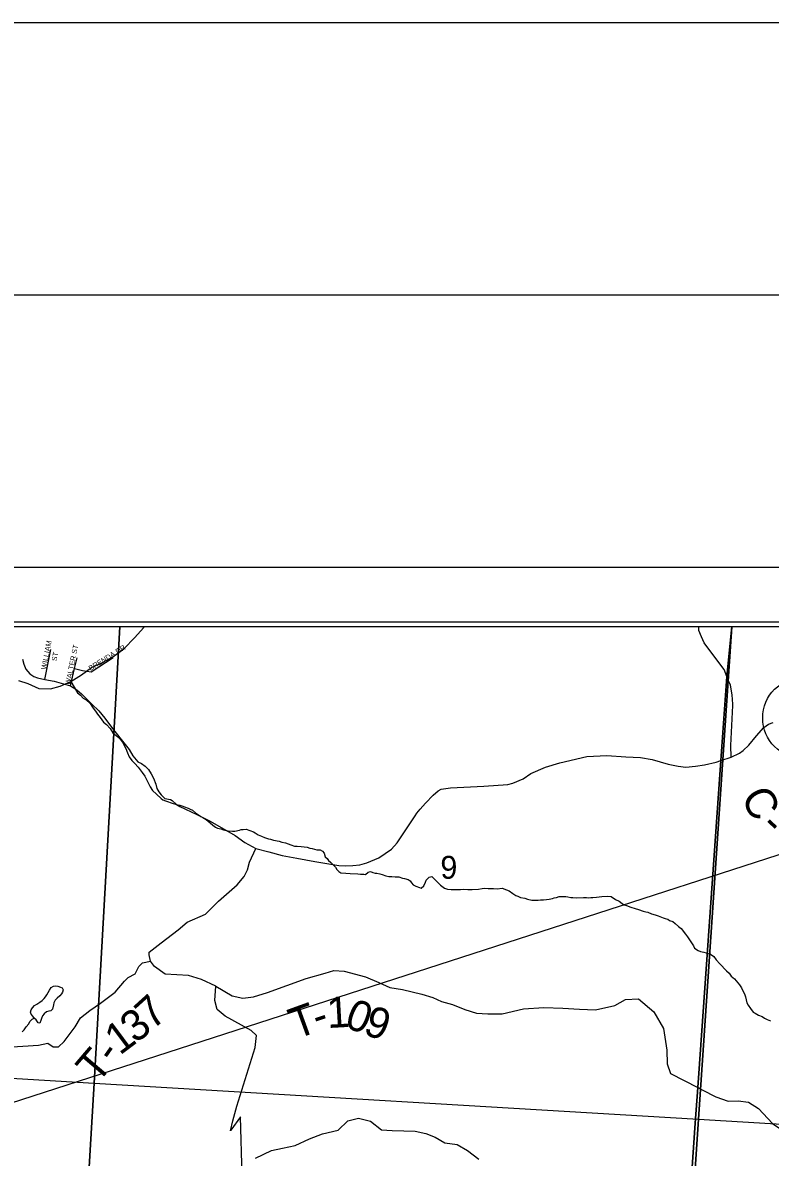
# Model space of a CAD drawing. Extents: x 0 to 34, y 0 to 22.
# Drawn here: x 4.684 to 6.056, y 19.917 to 22 of the extents above; entities that cross this region are included whole.
import ezdxf

# ---------------------------------------------------------------- set-up
doc = ezdxf.new("R2010")
doc.units = 0
for name, color, linetype in [('GM_X_County', 7, 'Continuous'), ('GM_X_County_Road', 7, 'Continuous'), ('GM_X_County_Road_Text', 7, 'Continuous'), ('GM_X_Minor_River', 7, 'Continuous'), ('GM_X_Section', 7, 'Continuous'), ('GM_X_Section_Text', 7, 'Continuous'), ('GM_X_State_Route', 7, 'Continuous'), ('GM_X_Township', 7, 'Continuous'), ('GM_X_Township_Road', 7, 'Continuous'), ('GM_X_Township_Road_Text', 7, 'Continuous'), ('GM_X_Township_ROW', 7, 'Continuous'), ('GM_X_Township_Subdivision', 7, 'Continuous'), ('GM_X_Township_Subdivision_Text', 7, 'Continuous'), ('GM_X_Unincorporated', 7, 'Continuous'), ('GM_X_US_Route', 7, 'Continuous'), ('SH_Border', 7, 'Continuous'), ('SH_Cut_Line', 7, 'Continuous'), ('SH_Data', 7, 'Continuous')]:
    doc.layers.add(name, color=color, linetype=linetype)

msp = doc.modelspace()

# ---------------------------------------------------------------- linework, layer by layer
at = {"layer": 'GM_X_County'}
msp.add_lwpolyline([(8.9084, 15.63), (8.9084, 20.8908), (2.1084, 20.8908), (2.1084, 19.9847)], dxfattribs=at)
at = {"layer": 'GM_X_County_Road'}
for points in [[(5.0661, 19.9663), (5.0651, 19.965), (5.0699, 19.9834), (5.0771, 20.0105), (5.1106, 20.1184), (5.113, 20.14), (5.1034, 20.1496), (5.0555, 20.176), (5.0411, 20.188), (5.0363, 20.2047), (5.0387, 20.2311), (5.0123, 20.2431), (4.9883, 20.2503), (4.9451, 20.2527), (4.9259, 20.2671), (4.9187, 20.2767), (4.9163, 20.2886), (4.9163, 20.2935), (4.9379, 20.3102), (4.9691, 20.3342), (4.9859, 20.3486), (5.0195, 20.363), (5.0435, 20.387), (5.0778, 20.4168), (5.0904, 20.432), (5.0965, 20.4443), (5.1005, 20.4587), (5.1119, 20.4835)], [(5.0867, 19.8834), (5.0839, 19.9908), (5.0661, 19.9663)]]:
    msp.add_lwpolyline(points, dxfattribs=at)
at = {"layer": 'GM_X_Minor_River'}
for points in [[(4.6759, 20.792), (4.6933, 20.7866), (4.7137, 20.7774), (4.7349, 20.7766), (4.7524, 20.7819), (4.7721, 20.7901), (4.7918, 20.8022), (4.8101, 20.8158), (4.8313, 20.8256), (4.8495, 20.8354), (4.8693, 20.8505), (4.8898, 20.871), (4.9058, 20.8891), (4.9069, 20.8908)], [(4.7721, 20.7901), (4.7846, 20.7697), (4.7902, 20.7654), (4.7947, 20.7596), (4.8003, 20.7565), (4.8078, 20.7499), (4.8122, 20.743), (4.8185, 20.7338), (4.8211, 20.7303), (4.8262, 20.7242), (4.8322, 20.7153), (4.8378, 20.7115), (4.8444, 20.7037), (4.8496, 20.6957), (4.8586, 20.6887), (4.8627, 20.6845), (4.8682, 20.6771), (4.8704, 20.6729), (4.8733, 20.6672), (4.8762, 20.6595), (4.8795, 20.6519), (4.8843, 20.645), (4.8899, 20.6396), (4.8959, 20.633), (4.9033, 20.6234), (4.9081, 20.6165), (4.9128, 20.6065), (4.9179, 20.5966), (4.9224, 20.5904), (4.9294, 20.5831), (4.938, 20.5754), (4.9414, 20.573), (4.9463, 20.5714), (4.9497, 20.5702), (4.9561, 20.5675), (4.9598, 20.5663), (4.9685, 20.5635), (4.9723, 20.563), (4.976, 20.5622), (4.9809, 20.5602), (4.9877, 20.5578), (4.9911, 20.5559), (4.9956, 20.5539), (5.0012, 20.5489), (5.0109, 20.5422), (5.0143, 20.5407), (5.0207, 20.5368), (5.0281, 20.5309), (5.033, 20.5267), (5.0378, 20.5228), (5.0416, 20.5212), (5.0473, 20.5196), (5.0522, 20.518), (5.0574, 20.5168), (5.0608, 20.5163), (5.0688, 20.5155), (5.0733, 20.5154), (5.0817, 20.5175), (5.0851, 20.5182), (5.0885, 20.5185), (5.0938, 20.5188), (5.1074, 20.514), (5.1108, 20.5125), (5.116, 20.509), (5.122, 20.5062), (5.128, 20.5038), (5.1352, 20.5014), (5.1386, 20.5006), (5.1442, 20.4986), (5.1548, 20.4969), (5.1597, 20.4953), (5.1665, 20.4941), (5.1759, 20.4905), (5.1827, 20.4881), (5.1876, 20.4877), (5.1948, 20.4872), (5.2008, 20.4867), (5.2061, 20.4858), (5.211, 20.4842), (5.2152, 20.4838), (5.2239, 20.4814), (5.2299, 20.4809), (5.234, 20.4785), (5.2374, 20.4751), (5.2392, 20.4686), (5.2429, 20.4651), (5.2455, 20.4616), (5.2492, 20.4585), (5.2578, 20.4496), (5.2603, 20.445), (5.2644, 20.4412), (5.2678, 20.4392), (5.2773, 20.4383), (5.2848, 20.4374), (5.2992, 20.4372), (5.3037, 20.4367), (5.3098, 20.4363), (5.3132, 20.4358), (5.3182, 20.4399)], [(5.3182, 20.4399), (5.3224, 20.4414), (5.3269, 20.4398), (5.3307, 20.4386), (5.3341, 20.4381), (5.3394, 20.4373), (5.3435, 20.4361), (5.3503, 20.4337), (5.3559, 20.4324), (5.3612, 20.432), (5.3677, 20.4315), (5.3745, 20.4314), (5.3809, 20.4294), (5.385, 20.4285), (5.3915, 20.4269), (5.3952, 20.4242), (5.3978, 20.4204), (5.4007, 20.4169), (5.4056, 20.4145), (5.412, 20.4118), (5.4154, 20.411), (5.42, 20.4151), (5.4232, 20.4215), (5.4244, 20.4256), (5.4298, 20.4312), (5.4351, 20.4323), (5.444, 20.423), (5.4511, 20.4161), (5.4582, 20.4106), (5.4635, 20.409), (5.4703, 20.4081), (5.4752, 20.4084), (5.4877, 20.4082), (5.4934, 20.4089), (5.501, 20.4084), (5.5089, 20.4086), (5.5203, 20.4092), (5.5271, 20.4102), (5.5309, 20.4105), (5.5381, 20.41), (5.548, 20.4103), (5.5548, 20.4098), (5.5639, 20.4108), (5.5718, 20.408), (5.5767, 20.4056), (5.5838, 20.4009), (5.5894, 20.3974), (5.5928, 20.3962), (5.5977, 20.3939), (5.6056, 20.3922), (5.6105, 20.3906), (5.6184, 20.3886), (5.6218, 20.3889), (5.6302, 20.3888), (5.6343, 20.3891), (5.64, 20.3894), (5.6453, 20.39), (5.6503, 20.3907), (5.6564, 20.3917), (5.6598, 20.3928), (5.664, 20.3939), (5.6685, 20.3953), (5.675, 20.3956), (5.681, 20.3955), (5.6844, 20.3951), (5.6901, 20.3938), (5.6935, 20.3934), (5.7003, 20.3933), (5.7132, 20.3938), (5.7189, 20.3934), (5.7227, 20.3933), (5.7268, 20.3936), (5.7306, 20.3939), (5.7371, 20.3942), (5.7473, 20.3952), (5.7572, 20.3958), (5.764, 20.3956), (5.7722, 20.3898), (5.7786, 20.387), (5.7842, 20.3828), (5.788, 20.3801), (5.7925, 20.3788), (5.8, 20.3761), (5.8079, 20.3736), (5.8143, 20.3716), (5.8226, 20.3688), (5.8279, 20.3676), (5.8317, 20.3668), (5.8384, 20.3636), (5.8452, 20.3616), (5.8505, 20.36), (5.8595, 20.3565), (5.8633, 20.3553), (5.8682, 20.354), (5.8715, 20.3513), (5.8772, 20.3493), (5.8817, 20.3458), (5.8876, 20.3404), (5.8929, 20.3365), (5.9003, 20.3265), (5.904, 20.3215)], [(5.904, 20.3215), (5.9092, 20.3142), (5.915, 20.305), (5.9172, 20.3004), (5.924, 20.2965), (5.9281, 20.2945), (5.9342, 20.2933), (5.9387, 20.2921), (5.9462, 20.2897), (5.9526, 20.285), (5.957, 20.2789), (5.9637, 20.2719), (5.9756, 20.2588), (5.9808, 20.2549), (5.9845, 20.2492), (5.9905, 20.2445), (5.9998, 20.233), (6.0031, 20.228), (6.0093, 20.215), (6.0107, 20.2111), (6.0118, 20.2058), (6.0132, 20.2001), (6.0158, 20.1959), (6.0198, 20.1897), (6.0246, 20.1832), (6.0284, 20.1812), (6.0344, 20.1777), (6.0412, 20.1749), (6.0457, 20.1722), (6.0505, 20.1695), (6.0569, 20.1671)], [(4.6827, 20.1471), (4.6866, 20.1509), (4.6901, 20.1561), (4.6951, 20.1614), (4.6971, 20.1659), (4.7013, 20.17), (4.7048, 20.1718), (4.7022, 20.1757), (4.6992, 20.1795), (4.6981, 20.183), (4.6994, 20.1871), (4.7017, 20.1913), (4.7056, 20.1954), (4.7101, 20.1976), (4.7155, 20.2017), (4.7194, 20.2046), (4.7232, 20.208), (4.7259, 20.2114), (4.7283, 20.2147), (4.7306, 20.2192), (4.7333, 20.2234), (4.7361, 20.2283), (4.7407, 20.2308)], [(4.7407, 20.2308), (4.7441, 20.2315), (4.7486, 20.2307), (4.7531, 20.2291), (4.7565, 20.2275), (4.758, 20.2241), (4.7568, 20.2199), (4.7548, 20.2166), (4.7521, 20.2132), (4.7471, 20.2087), (4.7432, 20.2054), (4.7413, 20.2005), (4.7404, 20.1963), (4.7388, 20.1887), (4.7353, 20.1854), (4.7319, 20.1847), (4.7277, 20.1836), (4.7235, 20.1803), (4.72, 20.1761), (4.7184, 20.1716), (4.7172, 20.1678), (4.7156, 20.1629), (4.7122, 20.1637), (4.7085, 20.1687), (4.7048, 20.1718)], [(5.1115, 19.9152), (5.1403, 19.9288), (5.1608, 19.9333), (5.1843, 19.9385), (5.2101, 19.9506), (5.2344, 19.9596), (5.2632, 19.9663), (5.2807, 19.9837), (5.3004, 19.9882), (5.3223, 19.9828), (5.3427, 19.9668), (5.3624, 19.966), (5.3836, 19.9652), (5.4041, 19.9643), (5.4237, 19.9605), (5.4411, 19.9536), (5.4585, 19.9429), (5.4812, 19.9398), (5.5001, 19.9291), (5.5212, 19.9131)]]:
    msp.add_lwpolyline(points, dxfattribs=at)
at = {"layer": 'GM_X_Section'}
for p, q in [((4.8624, 20.8908), (3.7825, 20.8908)), ((5.9857, 20.8908), (4.8624, 20.8908)), ((7.0909, 20.8908), (5.9857, 20.8908))]:
    msp.add_line(p, q, dxfattribs=at)
for points in [[(3.7825, 20.8908), (3.731, 20.118), (4.8149, 20.0525), (4.8624, 20.8908)], [(4.8624, 20.8908), (4.8149, 20.0525), (5.9246, 19.9867), (5.9857, 20.8908)], [(5.9857, 20.8908), (5.9246, 19.9867), (7.0324, 19.92), (7.0909, 20.8908)]]:
    msp.add_lwpolyline(points, dxfattribs=at)
for points in [[(4.8149, 20.0525), (4.754, 19.0266), (3.6625, 19.0898), (3.731, 20.118)], [(5.9246, 19.9867), (5.8561, 18.9573), (4.754, 19.0266), (4.8149, 20.0525)], [(7.0324, 19.92), (6.9681, 18.8952), (5.8561, 18.9573), (5.9246, 19.9867)]]:
    msp.add_lwpolyline(points, close=True, dxfattribs=at)
at = {"layer": 'GM_X_State_Route'}
for points in [[(4.6833, 20.8314), (4.6859, 20.8219), (4.6894, 20.8128), (4.6968, 20.8043), (4.7042, 20.7997), (4.7113, 20.7972), (4.7242, 20.7939), (4.7418, 20.791), (4.7547, 20.7874), (4.7715, 20.7823), (4.7834, 20.7749), (4.7916, 20.7678), (4.8106, 20.7489), (4.8239, 20.7364), (4.8348, 20.7229), (4.8506, 20.7017), (4.8698, 20.6775), (4.8792, 20.6654), (4.8862, 20.6539), (4.8922, 20.6463), (4.8955, 20.6429), (4.9018, 20.6398), (4.9086, 20.6346), (4.9145, 20.6285), (4.9195, 20.6208), (4.9241, 20.6127), (4.9284, 20.602), (4.9301, 20.594), (4.9335, 20.5878), (4.9378, 20.582), (4.945, 20.5753), (4.9552, 20.5736), (4.9581, 20.5718), (4.966, 20.5642), (4.9726, 20.5605), (5.0037, 20.5463), (5.0282, 20.5339), (5.0737, 20.5075), (5.0915, 20.4947), (5.1119, 20.4835), (5.1355, 20.4777), (5.1601, 20.4709), (5.187, 20.4659), (5.2203, 20.4595), (5.2641, 20.4521), (5.2761, 20.4515), (5.2901, 20.4522), (5.3028, 20.4535), (5.3158, 20.4573), (5.3374, 20.4667), (5.3608, 20.4821), (5.3714, 20.4938), (5.4042, 20.5437), (5.4075, 20.5487), (5.4136, 20.5559)], [(5.4136, 20.5559), (5.4231, 20.5669), (5.4372, 20.5813), (5.4463, 20.5892), (5.4523, 20.5923), (5.469, 20.5949), (5.5303, 20.5982), (5.5747, 20.6011), (5.5834, 20.6033), (5.6027, 20.6113), (5.6167, 20.6211), (5.6433, 20.6332), (5.6698, 20.6411), (5.7197, 20.6526), (5.7562, 20.6541), (5.7908, 20.6521), (5.8182, 20.6505), (5.8397, 20.6468), (5.8689, 20.6387), (5.8872, 20.635), (5.9014, 20.6331), (5.9192, 20.6347), (5.9355, 20.6374), (5.9567, 20.6419), (5.9657, 20.645), (5.9846, 20.6514), (5.9997, 20.6584), (6.0064, 20.6633), (6.0171, 20.6732), (6.0309, 20.6907), (6.0446, 20.7055), (6.0532, 20.7119), (6.0615, 20.7151)]]:
    msp.add_lwpolyline(points, dxfattribs=at)
at = {"layer": 'GM_X_Township'}
for points in [[(5.9855, 20.8908), (2.1084, 20.8908), (2.1084, 19.9847)], [(5.9855, 20.8908), (5.9767, 20.7996), (5.9657, 20.645), (5.923, 20.0446), (5.9184, 19.9792), (5.8482, 18.9514), (5.3841, 18.9816), (4.8908, 19.0136), (4.7488, 19.0228), (4.6863, 18.0158)], [(4.6863, 18.0158), (4.7488, 19.0228), (4.8908, 19.0136), (5.3841, 18.9816), (5.8482, 18.9514), (5.9184, 19.9792), (5.923, 20.0446), (5.9657, 20.645), (5.9767, 20.7996), (5.9855, 20.8908)], [(8.9084, 15.63), (8.9084, 20.8908), (5.9855, 20.8908)]]:
    msp.add_lwpolyline(points, dxfattribs=at)
at = {"layer": 'GM_X_Township_Road'}
for points in [[(5.9872, 20.7459), (5.9873, 20.7489), (5.9863, 20.7658), (5.9832, 20.7836), (5.9798, 20.7916), (5.9767, 20.7996), (5.9717, 20.8123), (5.9583, 20.83), (5.9351, 20.8614), (5.9298, 20.8724), (5.9253, 20.8842), (5.9252, 20.8908)], [(5.9846, 20.6514), (5.9841, 20.673), (5.9872, 20.7459)], [(4.743, 20.1192), (4.7498, 20.1192), (4.7599, 20.1293), (4.78, 20.1561), (4.79, 20.1728), (4.8068, 20.1862), (4.8269, 20.1997), (4.8537, 20.2198), (4.8705, 20.2399), (4.8772, 20.2466), (4.8906, 20.2533), (4.8973, 20.2667), (4.904, 20.2734), (4.9187, 20.2767)], [(5.0387, 20.2311), (5.0684, 20.2131), (5.0881, 20.2085), (5.1078, 20.2115), (5.1332, 20.2191), (5.2044, 20.2449), (5.2392, 20.2548), (5.2552, 20.2597), (5.2741, 20.2582), (5.3131, 20.2479), (5.3374, 20.2373), (5.3578, 20.2286), (5.3809, 20.2248), (5.4165, 20.2164), (5.4366, 20.21), (5.4525, 20.2028), (5.473, 20.1971), (5.4957, 20.1879), (5.5169, 20.1815), (5.5377, 20.18), (5.5639, 20.1803), (5.6033, 20.1894), (5.6404, 20.1917), (5.6752, 20.1906), (5.7063, 20.1887), (5.7355, 20.1875), (5.7707, 20.1955), (5.7904, 20.2061), (5.8143, 20.2076), (5.8427, 20.1837), (5.8605, 20.153), (5.8661, 20.1131), (5.8669, 20.0884), (5.8733, 20.0706), (5.923, 20.0446), (5.9309, 20.0406)], [(5.9309, 20.0406), (5.9309, 20.0405), (5.9563, 20.0273), (5.979, 20.0197), (5.9975, 20.0201), (6.0165, 20.0178), (6.0347, 20.0064), (6.06, 19.9787), (6.0911, 19.9578), (6.0987, 19.9491), (6.1112, 19.9419), (6.1237, 19.9385), (6.1362, 19.9369), (6.161, 19.9285)]]:
    msp.add_lwpolyline(points, dxfattribs=at)
at = {"layer": 'GM_X_Township_ROW'}
msp.add_lwpolyline([(4.3374, 20.0868), (4.3438, 20.0864), (4.3505, 20.0876), (4.357, 20.091), (4.3636, 20.0946), (4.3691, 20.0989), (4.3755, 20.1016), (4.3793, 20.1028), (4.3834, 20.104), (4.3876, 20.1043), (4.3948, 20.1043), (4.4038, 20.1031), (4.4154, 20.1035), (4.713, 20.1226), (4.7297, 20.1259), (4.7398, 20.1192), (4.743, 20.1192)], dxfattribs=at)
at = {"layer": 'GM_X_Township_Subdivision'}
for points in [[(4.7242, 20.7939), (4.7356, 20.8493)], [(4.7715, 20.7823), (4.779, 20.8143), (4.7836, 20.8339)], [(4.779, 20.8143), (4.7939, 20.8107), (4.8097, 20.8082), (4.8502, 20.8341)]]:
    msp.add_lwpolyline(points, dxfattribs=at)
at = {"layer": 'GM_X_Unincorporated'}
msp.add_circle((6.1167, 20.7233), 0.0744, dxfattribs=at)
at = {"layer": 'GM_X_US_Route'}
msp.add_lwpolyline([(7.1693, 20.827), (4.6185, 20.0016)], dxfattribs=at)
at = {"layer": 'SH_Border'}
msp.add_lwpolyline([(1.5, 21.5), (33.5, 21.5), (33.5, 0.5), (1.5, 0.5)], close=True, dxfattribs=at)
at = {"layer": 'SH_Cut_Line'}
msp.add_lwpolyline([(0, 0), (34, 0), (34, 22), (0, 22)], close=True, dxfattribs=at)
at = {"layer": 'SH_Data'}
for p, q in [((2, 21), (9, 21)), ((2.1, 20.9), (8.9, 20.9))]:
    msp.add_line(p, q, dxfattribs=at)

# ---------------------------------------------------------------- texts
at = {"layer": 'GM_X_County_Road_Text'}
for s, rotation, p in [('C', 298.2217, (6.0011, 20.5782)), ('-', 316.97, (6.0355, 20.5211))]:
    msp.add_text(s, height=0.0568, rotation=rotation, dxfattribs=at).set_placement(p)
at = {"layer": 'GM_X_Section_Text'}
msp.add_text('9', height=0.0419, rotation=0, dxfattribs=at).set_placement((5.4506, 20.4281))
at = {"layer": 'GM_X_Township_Road_Text'}
for s, rotation, p in [('7', 42.1376, (4.9221, 20.1489)), ('1', 3.2092, (5.2435, 20.1538)), ('T', 19.8984, (5.1857, 20.1329)), ('0', 338.9561, (5.2722, 20.1568)), ('9', 340.7228, (5.3067, 20.1435)), ('3', 37.7367, (4.8908, 20.1244)), ('-', 18.3664, (5.2252, 20.1472)), ('1', 36.7731, (4.8619, 20.1028)), ('T', 49.6158, (4.8208, 20.05)), ('-', 55.1548, (4.8519, 20.0871))]:
    msp.add_text(s, height=0.0568, rotation=rotation, dxfattribs=at).set_placement(p)
at = {"layer": 'GM_X_Township_Subdivision_Text'}
for s, rotation, p in [('WILLIAM', 78.8733, (4.7268, 20.8117)), ('WALTER ST', 78.4066, (4.771, 20.7834)), ('BRENDA DR', 31.9307, (4.8085, 20.8095)), ('ST', 79.3727, (4.7461, 20.827))]:
    msp.add_text(s, height=0.00947, rotation=rotation, dxfattribs=at).set_placement(p)

doc.saveas('drawing.dxf')
